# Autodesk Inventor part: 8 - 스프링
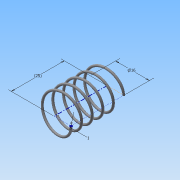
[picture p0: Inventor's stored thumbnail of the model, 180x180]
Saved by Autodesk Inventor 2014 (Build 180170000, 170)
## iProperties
Created: 2015-06
Part Number: 8 - 스프링
Material: 강철, 연강
Document SubType Name: Modeling
Designer: Administrator
Density: 7.86 g/cm^3
Appearance: 강철
Mass: 1.52988 g
Surface Area: 7.87024 cm^2
Volume: 0.194641 cm^3
Author: Administrator
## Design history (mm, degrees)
sketch "스케치1"
  geometry: L1 (0, 0)-(8, 0); L2 (8, 0)-(8, 14.5); L3 (8, 14.5)-(0, 14.5); L4 (0, 14.5)-(0, 0); C1 r 0.5 at (8, 0)
  constraints: 8 end point, 2 parallel, 1 centre point, 1 coincident, 1 horizontal, 1 perpendicular
  dimensions: "d0" = 14.5 distance between parallel lines of L1 L3 (derived); "d1" = 16 diameter of L2 L4; "d2" = 1 diameter of C1
feature "코일1" sketch "스케치1" pitch "d3" = 10; turns "d5" = 5; dims "d4" = 14.5 (= d0), "d6" = 0, angle "d7" = 90 deg, angle "d8" = 90 deg, "d9" = 0, "d10" = 0
node "작업 평면1"
sketch "스케치2"
  geometry: L1 (-8.5, 0)-(-7.5, 0) reference; 1 further point
  constraints: 1 horizontal alignment
extrude "돌출1" cut sketch "스케치2" distance "d12" = 10; taper "d13" = 0 deg
node "작업 평면2"
sketch "스케치3"
  geometry: L1 (-7.5, 0)-(-8.5, 0) reference; 1 further point
  constraints: 1 horizontal alignment
extrude "돌출2" cut sketch "스케치3" stored distance "d15" = 10; taper "d16" = 0 deg
node "솔리드1"
node "절단 모서리 투영1"
node "절단 모서리 투영2"
other parameters: "d11" = 0, "d14" = 14.5 (= d0)
